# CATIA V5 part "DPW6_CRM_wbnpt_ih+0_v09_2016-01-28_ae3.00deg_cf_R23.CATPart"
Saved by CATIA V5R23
Part number: DPW6_CRM_wbnpt_ih+0_v09_2016-01-28_ae3
Bounding box of the stored display mesh (mm): x 2349.5 to 66711.883, y -0.001 to 29450.021, z -278.37 to 8715.76
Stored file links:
  C:\Users\mrg\work\AIAA_DPW\DPW6\DLR_meshes\all\3deg00\DPW6_CRM_wbnpt_ih+0_v09_2016-01-28_ae3.00deg_cf.CATPart

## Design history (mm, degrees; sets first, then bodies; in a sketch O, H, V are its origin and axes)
MechanicalRefPlane1 "xy-plane"
MechanicalRefPlane2 "yz-plane"
MechanicalRefPlane3 "zx-plane"
Set1
  DatumSurface1 to DatumSurface3
Body1 (main body)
